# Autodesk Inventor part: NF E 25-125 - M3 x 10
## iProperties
Comments: To add or edit properties for Autodesk Inventor files, use iProperties.
Created: 2004-01
Part Number: NF E 25-125 - M3 x 10
Vendor: Autodesk Inc.
Document SubType Name: Modeling
Designer: Administrator
Material: Default
Description: Cylinder Head Cap Screw
Standard: NF E 25-125
Size Designation: M3 x 10
Density: 1 g/cm^3
Alert: To add or edit properties for Autodesk Inventor files, use iProperties.
Control State: 0
Master: False
Checked Out: False
Shininess: 64.0
Length Units: 11269
Angle Units: 11279
Time Units: 11290
Mass Units: 11283
Length Display Precision: 3
Angle Display Precision: 2
Compacted: True
EGR: 1
Density: 0.0
Volumn: 0.0
Area: 0.0
PropertySet Name: Model Information
Author: Administrator
Revision Number: 8
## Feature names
1. Body [Revolution]
2. Slot [Extrusion]
3. Fillet1
4. Chamfer1
